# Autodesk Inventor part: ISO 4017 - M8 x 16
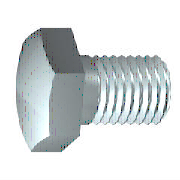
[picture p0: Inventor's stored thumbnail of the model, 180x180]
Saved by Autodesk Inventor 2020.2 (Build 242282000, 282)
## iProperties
Manager: www.cadconsulting.pl
Company: Fabian Stasiak CAD Consulting
Created: 2011-02
Part Number: ISO 4017 - M8 x 16
Material: Stal nierdzewna, 440C
Description: Wkręty z łbem sześciokątnym
Document SubType Name: Modeling
Standard: ISO 4017
Designer: F.Stasiak
Standard Revision: Third edition 1999-08-15
Standards Organization: ISO
Language: pl-PL
Size Designation: M8 x 16
Categories: <MemberInstance><Categories><Category DisplayName="Mocowania" InternalName="e4da775c-781d-43d5-af7c-5136215cf5a6" Mnemonic="FSTN"><Category DisplayName="Śruby"
Density: 7.75 g/cm^3
Appearance: Metal-Stal
IsCustomPart: 0
Author: F.Stasiak
Subject: Zbiór ćwiczeń. Autodesk Inventor 2020. Kurs podstawowy
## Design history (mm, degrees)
sketch "Szkic1"
  geometry: L1 (0, 5.815)-(0, 4); L2 (4, 4)-(16, 4); L3 (16, 4)-(16, 0); L4 (16, 0)-(-0.6, 0); L5 (-3.92, 0)-(19.32, 0) reference; L6 (-0.6, 0)-(-0.6, 5.815); L7 (-0.6, 5.815)-(0, 5.815); L8 (4, 4)-(3.233, 4); L9 (3.233, 4)-(0, 4); L10 (0, -1.163)-(0, 6.978) reference
  constraints: 16 end point, 2 collinear, 2 perpendicular, 1 parallel
  dimensions: "d0" = 16 distance between parallel lines of L3 L1 (= NLG); "d1" = 12 distance from line of L2.start L3 (= GEL); "d2" = 8 diameter of L2 L4 (= GD); "d9" = 0.6001 distance between parallel lines of L6 L1 (computed from SD); "d10" = 11.63 diameter of L7 L4 (= SD2); "d13" = 0.76691 distance of L2.start L8.end (computed from GAL); "d14" = 8 diameter of L9 L4 (= BDM)
revolve "Bryła" sketch "Szkic1" stored, may be unused: angle "d12" = 90 deg
sketch "Szkic2"
  geometry: L1 (0, 7.506)-(6.5, 3.753); L2 (6.5, 3.753)-(6.5, -3.753); L3 (6.5, -3.753)-(0, -7.506); L4 (0, -7.506)-(-6.5, -3.753); L5 (-6.5, -3.753)-(-6.5, 3.753); L6 (-6.5, 3.753)-(0, 7.506); 2 further points
  constraints: 12 end point, 1 coincident, 1 vertical, 11 other
  dimensions: "d11" = 13 distance between parallel lines of L5 L2 (= SW)
extrude "Głowica" join sketch "Szkic2" distance "d3" = 4.7 (= KOH - SD); taper "d4" = 0 deg
sketch "Szkic4"
  geometry: L1 (-5.3, 6.5)-(-5.3, 7.506); L2 (-5.3, 7.506)-(-4.72, 7.506); L3 (-4.72, 7.506)-(-5.3, 6.5); L4 (-6.24, 0)-(0.34, 0) reference; L5 (-0.6, 7.506)-(-5.3, 7.506) reference; L6 (-5.3, 3.753)-(-5.3, 7.506) reference
  constraints: 6 end point, 2 collinear, 1 perpendicular, 1 vertical
  dimensions: "d5" = 30 deg angle of L3 L1 (= ANG1); "d19" = 13 diameter of L1.start L4 (= SW0)
revolve "Faza1" sketch "Szkic4" stored, may be unused: angle "d21" = 90 deg
workplane "Work Plane1"
body "Solid1"
feature "Gwint" dims "d15" = 12 (= GEL), "d16" = 0
chamfer "Faza2" distance "d6" = 0.76681 (= -0.5 x SPD + 0.5 x GD); stored, may be unused: second distance "d7" = 0.76691 (computed from GUL), angle "d55" = 45 deg
other parameters: "NLG" = 16 [user parameter; used in 1 equation term], "GD" = 8 (= NND) [user parameter; used in 2 equation terms], "BDM" = 8 (= NND) [user parameter; used in 1 equation term], "KOH" = 5.3 [user parameter; used in 1 equation term], "GEL" = 12 [user parameter; used in 2 equation terms], "SW" = 13 [user parameter; used in 2 equation terms], "SW0" = 13 (= SW) [user parameter; used in 1 equation term], "SPD" = 6.46637 (= NND - 1.2269 x PTC) [user parameter; used in 1 equation term], "SD2" = 11.63 [user parameter; used in 2 equation terms], "SD" = 0.6 [user parameter; used in 2 equation terms], "ANG1" = 30 deg [user parameter; used in 1 equation term], "GAL" = 0.76681 (= 0.61345 x PTC) [user parameter; used in 1 equation term], "GUL" = 0.76681 (= 0.61345 x PTC) [user parameter; used in 1 equation term], "d8" = 0, "RR" = 0.4 [user parameter], "d57" = 0, "d58" = 0, "TPU" = 8 (computed from PTC) [user parameter], "GD1" = 6.46637 (= THREADDIA - 1.2269 x PTC) [user parameter], "THREADDIA" = 8 [user parameter; used in 1 equation term], "SDH" = 11.63 (= SD2) [user parameter], "SDHG" = 4 [user parameter], "TOA" = 30 deg [user parameter], "PTC" = 1.25 [user parameter; used in 5 equation terms], "NND" = 8 [user parameter; used in 3 equation terms], "E0" = 15.015 [user parameter]
